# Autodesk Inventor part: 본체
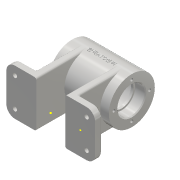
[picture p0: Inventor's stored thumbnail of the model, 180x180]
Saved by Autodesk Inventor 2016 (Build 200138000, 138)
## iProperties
Created: 2017-02
Part Number: 본체
Material: 알루미늄 6061
Document SubType Name: Modeling
Designer: H
Mass: 354.079 g
Surface Area: 425.199 cm^2
Volume: 131.14 cm^3
Density: 2.7 g/cm^3
Appearance: 알루미늄 - 평지
Author: H
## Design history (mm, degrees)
sketch "스케치1"
  geometry: L1 (52, -27)-(52, 27); L2 (-52, 27)-(-52, -27); L3 (0, 0)-(0, -48.333); L4 (17, 27)-(17, -27); L5 (-17, 27)-(-17, -27); L6 (52, 27)-(17, 27); L7 (-17, 27)-(-52, 27); L8 (-52, -27)-(-17, -27); L9 (17, -27)-(52, -27)
  constraints: 18 end point, 6 perpendicular, 5 parallel, 2 horizontal, 1 vertical
  dimensions: "d0" = 104 distance between parallel lines of L2 L1; "d2" = 52 distance between parallel lines of L1 L3; "d3" = 17 distance between parallel lines of L3 L4; "d4" = 17 distance between parallel lines of L3 L5; "d5" = 54 distance between parallel lines of L8 L7; "d6" = 54 distance between parallel lines of L6 L9
extrude "돌출1" new body sketch "스케치1" distance "d7" = 8; taper "d8" = 0 deg
fillet "모깎기1" dims "d9" = 10
sketch "스케치3"
  geometry: L1 (-17, -27)-(-17, 27) reference; L2 (17, 27)-(17, -27) reference; L3 (-42, 27)-(-17, 27) reference; L4 (-25, 27)-(-25, -27); L5 (-42, -27)-(-17, -27) reference; L6 (17, 27)-(42, 27) reference; L7 (25, 27)-(25, -27); L8 (42, -27)-(17, -27) reference; 1 further point
  constraints: 4 end point, 4 point on line, 2 perpendicular
  dimensions: "d10" = 8 distance between parallel lines of L1 L4; "d11" = 8 distance between parallel lines of L2 L7
extrude "돌출2" join sketch "스케치3" distance "d12" = 52; taper "d13" = 0 deg
sketch "스케치4"
  geometry: L1 (-25, 8)-(-25, 60) reference; L2 (25, 60)-(17, 60) reference; L3 (-17, 0)-(-42, 0) reference; L4 (25, 8)-(25, 60) reference; L5 (-35, 60)-(35, 60); L6 (-35, 60)-(-35, 87); L7 (-35, 87)-(35, 87); L8 (35, 87)-(35, 60); L9 (0, 0)-(0, 139.91); L10 (0, 0)-(139.91, 0)
  constraints: 12 end point, 3 perpendicular, 2 horizontal, 1 vertical
  dimensions: "d15" = 60 distance between parallel lines of L5 L3; "d18" = 35 distance between parallel lines of L9 L6; "d19" = 70 distance between parallel lines of L8 L6; "d20" = 54 diameter of L7 L5
revolve "회전1" sketch "스케치4" stored, may be unused: angle "d21" = 90 deg
sketch "스케치5"
  geometry: 1 further point
sketch "스케치6"
  geometry: C1 r 27 at (0, 0) reference; C2 r 16 at (0, 0); 1 further point
  constraints: 1 centre point, 1 coincident
  dimensions: "d22" = 32 diameter of C2
extrude "돌출3" cut sketch "스케치6" distance "d23" = 12; taper "d24" = 0 deg
sketch "스케치7"
  geometry: C1 r 27 at (0, 0) reference; C2 r 14 at (0, 0); 1 further point
  constraints: 1 centre point, 1 coincident
  dimensions: "d25" = 28 diameter of C2
extrude "돌출4" cut sketch "스케치7" distance "d26" = 3; taper "d27" = 0 deg
sketch "스케치8"
  geometry: C1 r 27 at (0, 0) reference; C2 r 22 at (0, 0); 1 further point
  constraints: 1 centre point, 1 coincident
  dimensions: "d28" = 44 diameter of C2
extrude "돌출5" cut sketch "스케치8" distance "d29" = 40; taper "d30" = 0 deg
sketch "스케치9"
  geometry: C1 r 27 at (0, 0) reference; C2 r 16 at (0, 0); 1 further point
  constraints: 1 centre point, 1 coincident
  dimensions: "d31" = 32 diameter of C2
extrude "돌출6" cut sketch "스케치9" distance "d32" = 12; taper "d33" = 0 deg
sketch "스케치10"
  geometry: C1 r 16 at (0, 0) reference; C2 r 27 at (0, 0) reference; C3 r 14 at (0, 0); 1 further point
  constraints: 1 centre point, 1 coincident
  dimensions: "d34" = 28 diameter of C3
extrude "돌출7" cut sketch "스케치10" distance "d35" = 12; taper "d36" = 0 deg
sketch "스케치11"
  geometry: L1 (-10, 92)-(-5, 92); L2 (-5, 92)-(-5, 83.453); L3 (-5, 83.453)-(-10, 83.453); L4 (-10, 83.453)-(-10, 92); L5 (-35, 33)-(-35, 87) reference; L6 (-35, 87)-(35, 87) reference; 1 further point
  constraints: 8 end point, 2 parallel, 1 horizontal, 1 perpendicular
  dimensions: "d37" = 25 distance between parallel lines of L5 L4; "d38" = 5 distance between parallel lines of L6 L1; "d39" = 10 diameter of L2 L4
revolve "회전2" sketch "스케치11" stored, may be unused: angle "d40" = 90 deg
sketch "스케치12"
  geometry: C1 r 5 at (0, 0) reference; 1 further point
hole "구멍1" sketch "스케치12" at (0, 0) diameter "d41" = 5.188; stored, may be unused: countersink angle "d45" = 90 deg, drill point angle "d47" = 118 deg; dims "d42" = 12, "d43" = 4, "d44" = 2, "d46" = 20.25
sketch "스케치13" dims "d48" = 42
  geometry: L1 (0, 0)-(0, 31.509); C1 r 16 at (0, 0) reference; C2 r 27 at (0, 0) reference; C3 r 16 at (0, 0) reference; 2 further points
  constraints: 2 end point, 1 coincident, 1 point on line, 1 vertical, 1 vertical alignment, 2 other
hole "구멍2" sketch "스케치13" at (0, 21) diameter "d49" = 3.242; stored, may be unused: countersink angle "d53" = 90 deg, drill point angle "d55" = 118 deg; dims "d50" = 8, "d51" = 4, "d52" = 2, "d54" = 10
sketch "스케치14"
  geometry: L1 (43.011, -18.187)-(38.108, -21.371); L2 (38.108, -21.371)-(34.84, -16.339); L3 (34.84, -16.339)-(39.744, -13.155); L4 (39.744, -13.155)-(43.011, -18.187); L5 (60, 0)-(18.199, 0); L6 (39.744, -13.155)-(60, 0); C1 r 27 at (60, 0) reference; C2 r 14 at (60, 0) reference; 1 further point
  constraints: 12 end point, 2 parallel, 1 horizontal, 1 perpendicular
  dimensions: "d59" = 33 deg angle of L5 L3; "d60" = 30 distance from line of L5.start L2; "d61" = 5.84691 distance between parallel lines of L2 L4; "d62" = 12 diameter of L1 L3; "d100" = 33 deg angle of L5 L6
revolve "회전3" sketch "스케치14" stored, may be unused: angle "d63" = 90 deg
sketch "스케치15"
  geometry: C1 r 6 at (0, 0) reference; 1 further point
hole "구멍3" sketch "스케치15" at (0, 0) diameter "d64" = 5.188; stored, may be unused: countersink angle "d68" = 90 deg, drill point angle "d70" = 118 deg; dims "d65" = 12, "d66" = 4, "d67" = 2, "d69" = 16
sketch "스케치16"
  geometry: 1 further point
node "작업 평면1"
sketch "스케치17"
  geometry: L1 (-35, 87)-(35, 87) reference; L2 (-35, 33)-(-35, 87) reference; 2 further points
  constraints: 1 other
  dimensions: "d72" = 27 distance from line of L1 point (0, 60); "d73" = 35 distance from line of point (0, 60) L2
feature "엠보싱1" sketch "스케치17" dims "d74" = 0.5, "d75" = 0
sketch "스케치18"
  geometry: A1 r 10 centre (42, 17) between (52, 17) and (42, 27) reference; A2 r 10 centre (42, -17) between (42, -27) and (52, -17) reference; A3 r 10 centre (-42, -17) between (-52, -17) and (-42, -27) reference; A4 r 10 centre (-42, 17) between (-42, 27) and (-52, 17) reference; 1 further point
hole "구멍4" sketch "스케치18" at (42, 17), (42, -17), (-42, -17), (-42, 17) diameter "d76" = 5; stored, may be unused: countersink angle "d80" = 90 deg, drill point angle "d82" = 118 deg; dims "d77" = 12, "d78" = 9, "d79" = 3, "d81" = 16
sketch "스케치19"
  geometry: L1 (39.402, 12.5)-(36.804, 17); L2 (36.804, 17)-(39.402, 21.5); L3 (39.402, 21.5)-(44.598, 21.5); L4 (44.598, 21.5)-(47.196, 17); L5 (47.196, 17)-(44.598, 12.5); L6 (44.598, 12.5)-(39.402, 12.5); L7 (39.402, -21.5)-(36.804, -17); L8 (36.804, -17)-(39.402, -12.5); L9 (39.402, -12.5)-(44.598, -12.5); L10 (44.598, -12.5)-(47.196, -17); L11 (47.196, -17)-(44.598, -21.5); L12 (44.598, -21.5)-(39.402, -21.5); L13 (-44.598, -21.5)-(-47.196, -17); L14 (-47.196, -17)-(-44.598, -12.5); L15 (-44.598, -12.5)-(-39.402, -12.5); L16 (-39.402, -12.5)-(-36.804, -17); L17 (-36.804, -17)-(-39.402, -21.5); L18 (-39.402, -21.5)-(-44.598, -21.5); L19 (-44.598, 12.5)-(-47.196, 17); L20 (-47.196, 17)-(-44.598, 21.5); L21 (-44.598, 21.5)-(-39.402, 21.5); L22 (-39.402, 21.5)-(-36.804, 17); L23 (-36.804, 17)-(-39.402, 12.5); L24 (-39.402, 12.5)-(-44.598, 12.5); C1 r 2.5 at (42, -17) reference; C2 r 2.5 at (-42, -17) reference; C3 r 2.5 at (-42, 17) reference; 15 further points
  constraints: 48 end point, 5 coincident, 4 midpoint, 4 vertical alignment, 1 point on line, 56 other
extrude "돌출8" cut sketch "스케치19" distance "d83" = 3; taper "d84" = 0 deg
extrude "돌출9" cut sketch "스케치19" distance "d85" = 3; taper "d86" = 0 deg
fillet "모깎기2" dims "d87" = 2
fillet "모깎기3" dims "d88" = 2
fillet "모깎기4" dims "d89" = 2
fillet "모깎기5" dims "d90" = 3
fillet "모깎기6" dims "d91" = 0.3
chamfer "모따기1" distance "d92" = 1; stored, may be unused: second distance "d93" = 2, angle "d94" = 45 deg
chamfer "모따기2" distance "d95" = 1; stored, may be unused: second distance "d96" = 2, angle "d97" = 45 deg
fillet "모깎기7" dims "d98" = 2
node "솔리드1"
pattern_circular "원형 패턴1" dims angle "d57" = 360 deg
mirror "대칭1"
node "투영된 루프1"
node "투영된 루프2"
node "투영된 루프3"
other parameters: "d1" = 54, "d71" = 32.5
